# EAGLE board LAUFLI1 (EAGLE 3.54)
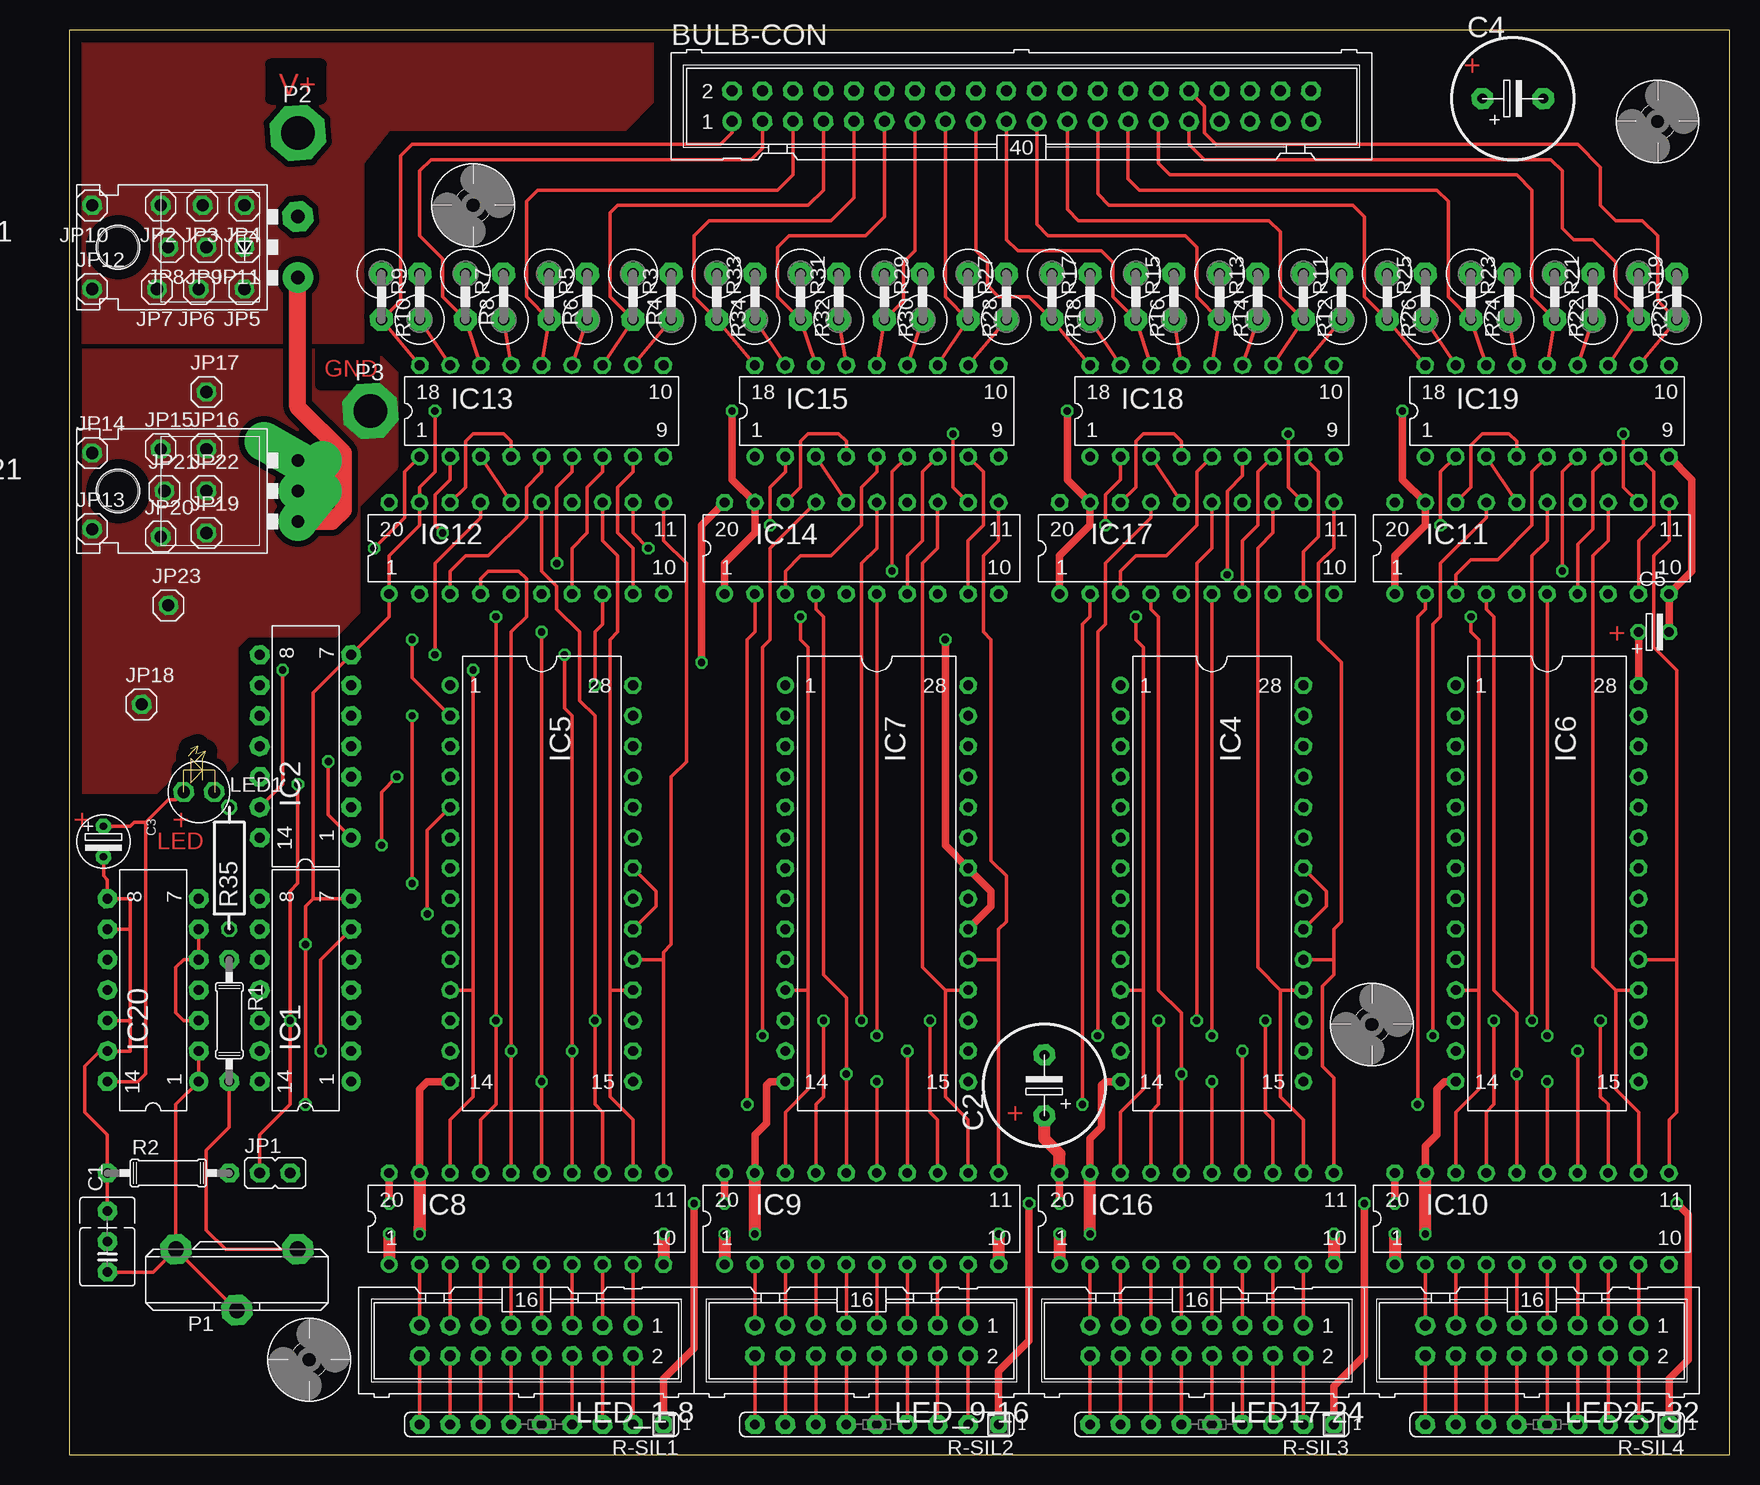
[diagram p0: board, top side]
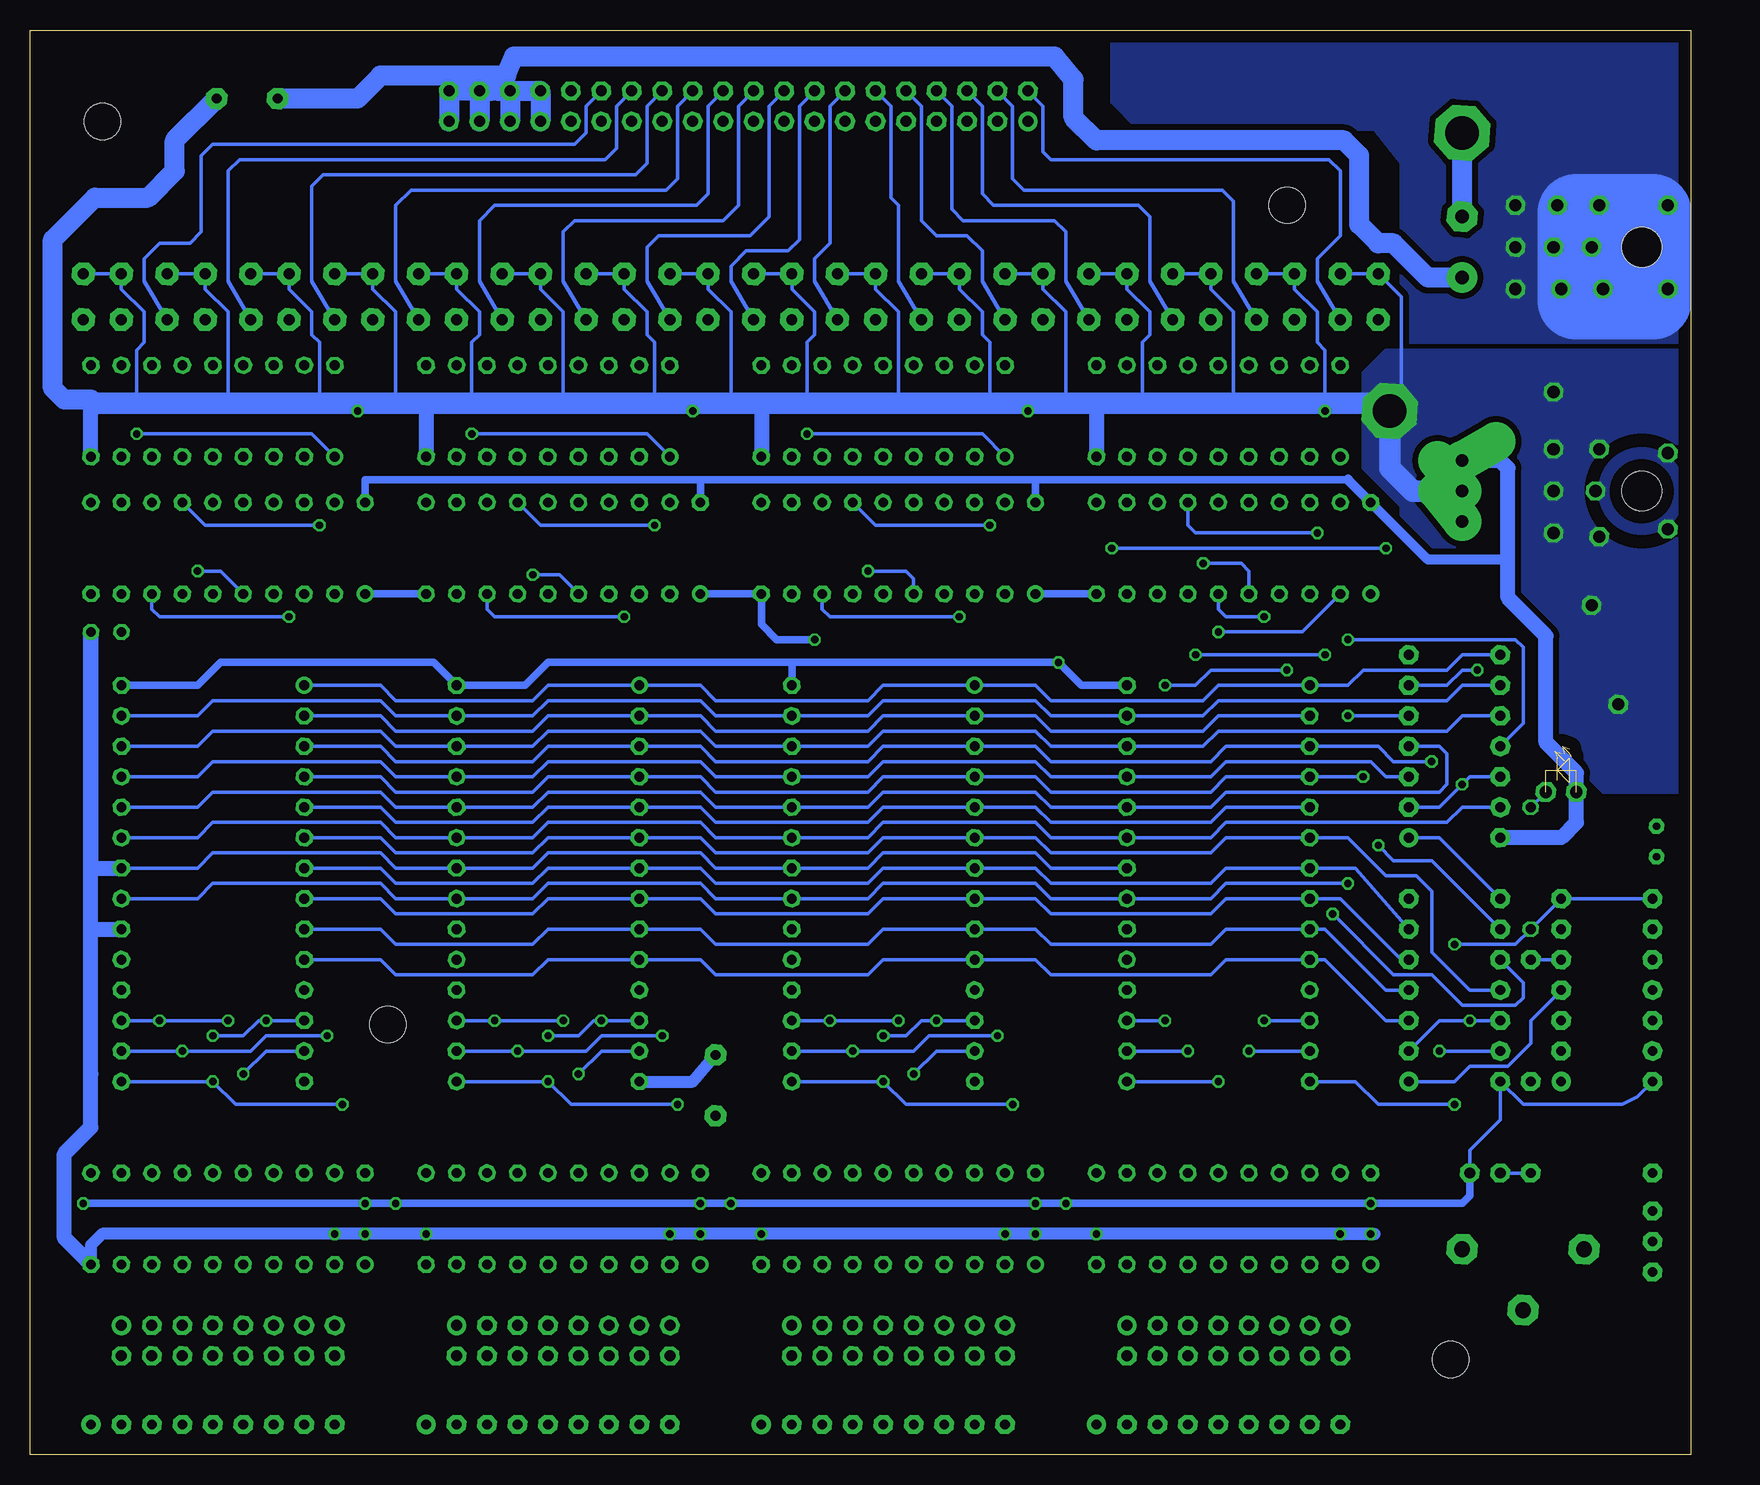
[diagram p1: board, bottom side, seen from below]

Size 138.43 x 118.75 mm. Coordinates in mm from the lower left corner, seen from the top.
Outline: 0,0 138.43,0 138.43,118.75 0,118.75 0,0
Copper layers used: Top, Bottom
tRestrict: area 16.8,113 to 21,115.9; area 21,89.2 to 25.4,92.1

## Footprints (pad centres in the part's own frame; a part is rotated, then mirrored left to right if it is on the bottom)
40 = drill 0.914 pad 1.6 round:  -24.13,-1.27 | drill 0.914 pad 1.6 octagon:  -24.13,1.27;  -21.59,-1.27;  -21.59,1.27;  -19.05,-1.27;  -19.05,1.27;  -16.51,-1.27;  -16.51,1.27;  -13.97,-1.27;  -13.97,1.27;  -11.43,-1.27;  -11.43,1.27;  -8.89,-1.27;  -8.89,1.27;  -6.35,-1.27;  -6.35,1.27;  -3.81,-1.27;  -3.81,1.27;  -1.27,-1.27;  -1.27,1.27;  1.27,-1.27;  1.27,1.27;  3.81,-1.27;  3.81,1.27;  6.35,-1.27;  6.35,1.27;  8.89,-1.27;  8.89,1.27;  11.43,1.27;  11.43,-1.27;  13.97,-1.27;  13.97,1.27;  16.51,1.27;  16.51,-1.27;  19.05,-1.27;  19.05,1.27;  21.59,1.27;  21.59,-1.27;  24.13,-1.27;  24.13,1.27
,5/5-5 = drill 0.813 pad 1.6 octagon:  -2.54,0;  2.54,0;  0,0
ELK5 = drill 0.813 pad 1.778 octagon:  -2.54,0;  2.54,0
ELK2,5 = drill 0.61 pad 1.27 octagon:  -1.27,0;  1.27,0
ELK2,5' = drill 0.813 pad 1.3 octagon:  0,0;  2.54,0
220ACK = drill 1.118 pad 2.54 round:  -2.54,-3.81 | drill 1.118 pad 2.54 octagon:  2.54,-3.81 | hole 3.302: 0,11.176
L14 = drill 0.813 pad 1.6 round:  -7.62,-3.81 | drill 0.813 pad 1.6 octagon:  -5.08,-3.81;  -2.54,-3.81;  0,-3.81;  2.54,-3.81;  5.08,-3.81;  7.62,-3.81;  7.62,3.81;  5.08,3.81;  2.54,3.81;  0,3.81;  -2.54,3.81;  -5.08,3.81;  -7.62,3.81
L28 = drill 0.813 pad 1.422 round:  -16.51,-7.62 | drill 0.813 pad 1.422 octagon:  -13.97,-7.62;  -11.43,-7.62;  -8.89,-7.62;  -6.35,-7.62;  -3.81,-7.62;  -1.27,-7.62;  1.27,-7.62;  3.81,-7.62;  6.35,-7.62;  8.89,-7.62;  11.43,-7.62;  13.97,-7.62;  16.51,-7.62;  16.51,7.62;  13.97,7.62;  11.43,7.62;  8.89,7.62;  6.35,7.62;  3.81,7.62;  1.27,7.62;  -1.27,7.62;  -3.81,7.62;  -6.35,7.62;  -8.89,7.62;  -11.43,7.62;  -13.97,7.62;  -16.51,7.62
L20 = drill 0.813 pad 1.397 round:  -11.43,-3.81 | drill 0.813 pad 1.397 octagon:  -8.89,-3.81;  -6.35,-3.81;  -3.81,-3.81;  -1.27,-3.81;  1.27,-3.81;  3.81,-3.81;  6.35,-3.81;  8.89,-3.81;  11.43,-3.81;  11.43,3.81;  8.89,3.81;  6.35,3.81;  3.81,3.81;  1.27,3.81;  -1.27,3.81;  -3.81,3.81;  -6.35,3.81;  -8.89,3.81;  -11.43,3.81
L18 = drill 0.813 pad 1.422 round:  -10.16,-3.81 | drill 0.813 pad 1.422 octagon:  -7.62,-3.81;  -5.08,-3.81;  -2.54,-3.81;  0,-3.81;  2.54,-3.81;  5.08,-3.81;  7.62,-3.81;  10.16,-3.81;  10.16,3.81;  7.62,3.81;  5.08,3.81;  2.54,3.81;  0,3.81;  -2.54,3.81;  -5.08,3.81;  -7.62,3.81;  -10.16,3.81
L14' = drill 0.813 pad 1.6 round:  -7.62,-3.81 | drill 0.813 pad 1.6 octagon:  -5.08,-3.81;  7.62,-3.81;  7.62,3.81;  -2.54,-3.81;  0,-3.81;  5.08,-3.81;  2.54,-3.81;  5.08,3.81;  2.54,3.81;  0,3.81;  -2.54,3.81;  -5.08,3.81;  -7.62,3.81
XXL = drill 1.016 pad 3.251 offset:  -2.54,-3.81;  0,-3.81;  2.54,-3.81 | hole 3.302: 0,11.176
1 = drill 0.914 pad 1.6 octagon:  0,-1.27;  0,1.27
01 = drill 1.016 pad 1.6 octagon:  0,0
D-5 = drill 1.016 pad 1.676 octagon:  0,0;  2.54,0
16 = drill 0.914 pad 1.6 round:  -8.89,-1.27 | drill 0.914 pad 1.6 octagon:  -8.89,1.27;  -6.35,-1.27;  -6.35,1.27;  -3.81,-1.27;  -3.81,1.27;  -1.27,-1.27;  -1.27,1.27;  1.27,-1.27;  1.27,1.27;  3.81,-1.27;  3.81,1.27;  6.35,-1.27;  6.35,1.27;  8.89,-1.27;  8.89,1.27
15 = drill 1.321 pad 2.54 octagon:  -5.08,-2.54;  5.08,-2.54;  0,2.54
N3_81 = drill 2.794 pad 4.572 octagon:  0,0
07/10 = drill 0.813 pad 1.6 octagon:  -5.08,0;  5.08,0
11V = drill 0.914 pad 1.905 octagon:  -2.54,0;  1.27,0
0 = drill 0.813 pad 1.3 octagon:  0,0;  10.16,0
L9 = drill 0.813 pad 1.6 round:  -10.16,0 | drill 0.813 pad 1.6 octagon:  -7.62,0;  -5.08,0;  -2.54,0;  0,0;  2.54,0;  5.08,0;  7.62,0;  10.16,0
3,0 = hole 3.023: 0,0

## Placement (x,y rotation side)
BULB-CON  [40]  79.38,112.39 0 top
C1  330nF  [,5/5-5]  3.17,17.78 90 top
C2  1000uF/6.3V  [ELK5]  81.28,30.8 90 top
C3  4u7 Tantal  [ELK2,5]  2.86,51.12 270 top
C4  470uF/16V  [ELK5]  120.33,113.03 0 top
C5  4u7  [ELK2,5']  130.81,68.58 0 top
D1  MBR760  [220ACK]  15.24,100.65 90 top
IC1  74393  [L14]  19.68,38.73 90 top
IC2  74393  [L14]  19.68,59.05 90 top
IC4  27512  [L28]  95.25,47.62 270 top
IC5  27512  [L28]  39.37,47.62 270 top
IC6  27512  [L28]  123.19,47.62 270 top
IC7  27512  [L28]  67.31,47.62 270 top
IC8  74245  [L20]  38.1,19.68 0 top
IC9  74245  [L20]  66.04,19.68 0 top
IC10  74245  [L20]  121.92,19.68 0 top
IC11  74240  [L20]  121.92,75.56 0 top
IC12  74240  [L20]  38.1,75.56 0 top
IC13  ULN2803A  [L18]  39.37,87 0 top
IC14  74240  [L20]  66.04,75.56 0 top
IC15  ULN2803A  [L18]  67.31,87 0 top
IC16  74245  [L20]  93.98,19.68 0 top
IC17  74240  [L20]  93.98,75.56 0 top
IC18  ULN2803A  [L18]  95.25,87 0 top
IC19  ULN2803A  [L18]  123.19,87 0 top
IC20  4093  [L14']  6.99,38.73 90 top
IC21  7805  [XXL]  15.24,80.33 90 top
JP1  RESET  [1]  17.14,23.5 270 top
JP2  PINHD-1X1  [01]  7.62,104.14 180 top
JP3  PINHD-1X1  [01]  11.11,104.14 180 top
JP4  PINHD-1X1  [01]  14.61,104.14 180 top
JP5  PINHD-1X1  [01]  14.61,97.16 180 top
JP6  PINHD-1X1  [01]  10.79,97.16 180 top
JP7  PINHD-1X1  [01]  7.3,97.16 180 top
JP8  PINHD-1X1  [01]  8.26,100.65 180 top
JP9  PINHD-1X1  [01]  11.43,100.65 180 top
JP10  PINHD-1X1  [01]  1.91,104.14 180 top
JP11  PINHD-1X1  [01]  14.61,100.65 180 top
JP12  PINHD-1X1  [01]  1.91,97.16 0 top
JP13  PINHD-1X1  [01]  1.91,77.15 0 top
JP14  PINHD-1X1  [01]  1.91,83.5 0 top
JP15  PINHD-1X1  [01]  7.62,83.82 0 top
JP16  PINHD-1X1  [01]  11.43,83.82 0 top
JP17  PINHD-1X1  [01]  11.43,88.58 0 top
JP18  PINHD-1X1  [01]  6.03,62.55 0 top
JP19  PINHD-1X1  [01]  11.43,76.83 0 top
JP20  PINHD-1X1  [01]  7.62,76.52 0 top
JP21  PINHD-1X1  [01]  7.94,80.33 0 top
JP22  PINHD-1X1  [01]  11.43,80.33 0 top
JP23  PINHD-1X1  [01]  8.26,70.8 0 top
LED1  Power  [D-5]  9.53,55.24 0 top
LED17-24  ML16  [16]  93.98,9.53 180 top
LED25-32  ML16  [16]  121.92,9.53 180 top
LED_1-8  ML16  [16]  38.1,9.53 180 top
LED_9-16  ML16  [16]  66.04,9.53 180 top
P1  500K  [15]  13.97,14.61 180 top
P2  [N3_81]  19.05,110.17 0 top
P3  [N3_81]  25.08,87 0 top
R1  1K8  [07/10]  13.34,36.2 270 top
R2  330R  [07/10]  8.26,23.5 0 top
R3  220 Ohm  [11V]  50.16,97.16 90 top
R4  220 Ohm  [11V]  46.99,95.89 270 top
R5  220 Ohm  [11V]  43.18,97.16 90 top
R6  220 Ohm  [11V]  40.01,95.89 270 top
R7  220 Ohm  [11V]  36.2,97.16 90 top
R8  220 Ohm  [11V]  33.02,95.89 270 top
R9  220 Ohm  [11V]  29.21,97.16 90 top
R10  220 Ohm  [11V]  26.04,95.89 270 top
R11  220 Ohm  [11V]  106.05,97.16 90 top
R12  220 Ohm  [11V]  102.87,95.89 270 top
R13  220 Ohm  [11V]  99.06,97.16 90 top
R14  220 Ohm  [11V]  95.89,95.89 270 top
R15  220 Ohm  [11V]  92.08,97.16 90 top
R16  220 Ohm  [11V]  88.9,95.89 270 top
R17  220 Ohm  [11V]  85.09,97.16 90 top
R18  220 Ohm  [11V]  81.92,95.89 270 top
R19  220 Ohm  [11V]  133.99,97.16 90 top
R20  220 Ohm  [11V]  130.81,95.89 270 top
R21  220 Ohm  [11V]  127,97.16 90 top
R22  220 Ohm  [11V]  123.83,95.89 270 top
R23  220 Ohm  [11V]  120.02,97.16 90 top
R24  220 Ohm  [11V]  116.84,95.89 270 top
R25  220 Ohm  [11V]  113.03,97.16 90 top
R26  220 Ohm  [11V]  109.86,95.89 270 top
R27  220 Ohm  [11V]  78.11,97.16 90 top
R28  220 Ohm  [11V]  74.93,95.89 270 top
R29  220 Ohm  [11V]  71.12,97.16 90 top
R30  220 Ohm  [11V]  67.94,95.89 270 top
R31  220 Ohm  [11V]  64.14,97.16 90 top
R32  220 Ohm  [11V]  60.96,95.89 270 top
R33  220 Ohm  [11V]  57.15,97.16 90 top
R34  220 Ohm  [11V]  53.98,95.89 270 top
R35  330  [0]  13.34,43.81 90 top
R-SIL1  8x220 Ohm  [L9]  39.37,2.54 180 top
R-SIL2  8x220 Ohm  [L9]  67.31,2.54 180 top
R-SIL3  8x220 Ohm  [L9]  95.25,2.54 180 top
R-SIL4  8x220 Ohm  [L9]  123.19,2.54 180 top
U$2  [3,0]  20,7.94 0 top
U$3  [3,0]  33.66,104.14 0 top
U$4  [3,0]  108.58,35.88 0 top
U$5  [3,0]  132.4,111.12 0 top

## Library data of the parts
BULB-CON LED17-24 LED25-32 LED_1-8 LED_9-16 = CON-ML
C1 = CAP
C2-C4 P2 P3 R35 = MATHIAS2
C5 LED1 = MATHIA2A
D1 = DIODE
IC1 IC2 IC8-IC12 IC14 IC16 IC17 = 74XX
IC4-IC7 = MEMORY
IC13 IC15 IC18 IC19 = ULN
IC20 = 40XX
IC21 = V-REG
JP1 = JUMPS
JP2-JP23 = PINHEAD
P1 = TRIMPOT
R1-R34 = R
R-SIL1-R-SIL4 = R-SIL
U$2-U$5 = HOLES

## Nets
+5V: C2. C3. C5. IC1. IC2. IC4. IC5. IC6. IC7. IC8. IC9. IC10. IC11. IC12. IC14. IC16. IC17. IC20. IC21. JP1. LED1. R-SIL1. R-SIL2. R-SIL3. R-SIL4.
A0: IC1. IC4. IC5. IC6. IC7.
A1: IC1. IC4. IC5. IC6. IC7.
A2: IC1. IC4. IC5. IC6. IC7.
A3: IC1. IC4. IC5. IC6. IC7.
A4: IC1. IC4. IC5. IC6. IC7.
A5: IC1. IC4. IC5. IC6. IC7.
A6: IC1. IC4. IC5. IC6. IC7.
A7: IC1. IC2. IC4. IC5. IC6. IC7.
A8: IC2. IC4. IC5. IC6. IC7.
A9: IC2. IC4. IC5. IC6. IC7.
A10: IC2. IC4. IC5. IC6. IC7.
A11: IC2. IC4. IC5. IC6. IC7.
A12: IC2. IC4. IC5. IC6. IC7.
A13: IC2. IC4. IC5. IC6. IC7.
A14: IC2. IC4. IC5. IC6. IC7.
A15: IC2. IC4. IC5. IC6. IC7.
BULB1: BULB-CON. IC13. R10.
BULB2: BULB-CON. IC13. R9.
BULB3: BULB-CON. IC13. R8.
BULB4: BULB-CON. IC13. R7.
BULB5: BULB-CON. IC13. R6.
BULB6: BULB-CON. IC13. R5.
BULB7: BULB-CON. IC13. R4.
BULB8: BULB-CON. IC13. R3.
BULB9: BULB-CON. IC15. R34.
BULB10: BULB-CON. IC15. R33.
BULB11: BULB-CON. IC15. R32.
BULB12: BULB-CON. IC15. R31.
BULB13: BULB-CON. IC15. R30.
BULB14: BULB-CON. IC15. R29.
BULB15: BULB-CON. IC15. R28.
BULB16: BULB-CON. IC15. R27.
BULB17: BULB-CON. IC18. R18.
BULB18: BULB-CON. IC18. R17.
BULB19: BULB-CON. IC18. R16.
BULB20: BULB-CON. IC18. R15.
BULB21: BULB-CON. IC18. R14.
BULB22: BULB-CON. IC18. R13.
BULB23: BULB-CON. IC18. R12.
BULB24: BULB-CON. IC18. R11.
BULB25: BULB-CON. IC19. R26.
BULB26: BULB-CON. IC19. R25.
BULB27: BULB-CON. IC19. R24.
BULB28: BULB-CON. IC19. R23.
BULB29: BULB-CON. IC19. R22.
BULB30: BULB-CON. IC19. R21.
BULB31: BULB-CON. IC19. R20.
BULB32: BULB-CON. IC19. R19.
CLOCK: IC1. IC20.
D1: IC5. IC8. IC12.
D2: IC5. IC8. IC12.
D3: IC5. IC8. IC12.
D4: IC5. IC8. IC12.
D5: IC5. IC8. IC12.
D6: IC5. IC8. IC12.
D7: IC5. IC8. IC12.
D8: IC5. IC8. IC12.
D9: IC7. IC9. IC14.
D10: IC7. IC9. IC14.
D11: IC7. IC9. IC14.
D12: IC7. IC9. IC14.
D13: IC7. IC9. IC14.
D14: IC7. IC9. IC14.
D15: IC7. IC9. IC14.
D16: IC7. IC9. IC14.
D17: IC4. IC16. IC17.
D18: IC4. IC16. IC17.
D19: IC4. IC16. IC17.
D20: IC4. IC16. IC17.
D21: IC4. IC16. IC17.
D22: IC4. IC16. IC17.
D23: IC4. IC16. IC17.
D24: IC4. IC16. IC17.
D25: IC6. IC10. IC11.
D26: IC6. IC10. IC11.
D27: IC6. IC10. IC11.
D28: IC6. IC10. IC11.
D29: IC6. IC10. IC11.
D30: IC6. IC10. IC11.
D31: IC6. IC10. IC11.
D32: IC6. IC10. IC11.
GND: C1. C2. C3. C4. C5. IC1. IC2. IC4. IC5. IC6. IC7. IC8. IC9. IC10. IC11. IC12. IC13. IC14. IC15. IC16. IC17. IC18. IC19. IC20. IC21. JP13. JP14. JP15. JP16. JP17. JP18. JP19. JP20. JP21. JP22. JP23. P3. R2. R3. R4. R5. R6. R7. R8. R9. R10. R11. R12. R13. R14. R15. R16. R17. R18. R19. R20. R21. R22. R23. R24. R25. R26. R27. R28. R29. R30. R31. R32. R33. R34. R35.
N$1: IC20. R1.
N$2: P1. R1.
N$3: IC1. IC2. JP1. R2.
N$4: IC9. LED_9-16.
N$5: IC9. LED_9-16.
N$6: C1. IC20. P1.
N$7: IC9. LED_9-16.
N$8: IC9. LED_9-16.
N$9: IC9. LED_9-16.
N$10: IC9. LED_9-16.
N$11: IC9. LED_9-16.
N$12: IC9. LED_9-16.
N$13: IC8. LED_1-8.
N$14: IC8. LED_1-8.
N$15: IC8. LED_1-8.
N$16: IC8. LED_1-8.
N$17: IC8. LED_1-8.
N$18: IC8. LED_1-8.
N$19: IC8. LED_1-8.
N$20: IC8. LED_1-8.
N$21: LED_1-8. R-SIL1.
N$22: LED_1-8. R-SIL1.
N$23: LED_1-8. R-SIL1.
N$24: LED_1-8. R-SIL1.
N$25: LED_1-8. R-SIL1.
N$26: LED_1-8. R-SIL1.
N$27: LED_1-8. R-SIL1.
N$28: LED_1-8. R-SIL1.
N$29: LED_9-16. R-SIL2.
N$30: LED_9-16. R-SIL2.
N$31: LED_9-16. R-SIL2.
N$32: LED_9-16. R-SIL2.
N$33: LED_9-16. R-SIL2.
N$34: LED_9-16. R-SIL2.
N$35: LED_9-16. R-SIL2.
N$36: LED_9-16. R-SIL2.
N$37: IC14. IC15.
N$38: IC14. IC15.
N$39: IC14. IC15.
N$40: IC14. IC15.
N$41: IC14. IC15.
N$42: IC14. IC15.
N$43: IC14. IC15.
N$44: IC14. IC15.
N$45: IC16. LED17-24.
N$46: IC16. LED17-24.
N$47: IC16. LED17-24.
N$48: IC16. LED17-24.
N$49: IC16. LED17-24.
N$50: IC16. LED17-24.
N$51: IC16. LED17-24.
N$52: IC16. LED17-24.
N$53: IC10. LED25-32.
N$54: IC10. LED25-32.
N$55: IC10. LED25-32.
N$56: IC10. LED25-32.
N$57: IC10. LED25-32.
N$58: IC10. LED25-32.
N$59: IC10. LED25-32.
N$60: IC10. LED25-32.
N$61: LED25-32. R-SIL4.
N$62: LED25-32. R-SIL4.
N$63: LED25-32. R-SIL4.
N$64: LED25-32. R-SIL4.
N$65: LED25-32. R-SIL4.
N$66: LED25-32. R-SIL4.
N$67: LED25-32. R-SIL4.
N$68: LED25-32. R-SIL4.
N$69: IC11. IC19.
N$70: IC11. IC19.
N$71: IC11. IC19.
N$72: IC11. IC19.
N$73: IC11. IC19.
N$74: IC11. IC19.
N$75: IC11. IC19.
N$76: IC11. IC19.
N$77: LED1. R35.
N$78: D1. P2.
N$101: IC12. IC13.
N$102: IC12. IC13.
N$103: IC12. IC13.
N$104: IC12. IC13.
N$105: IC12. IC13.
N$106: IC12. IC13.
N$107: IC12. IC13.
N$108: IC12. IC13.
N$109: LED17-24. R-SIL3.
N$110: LED17-24. R-SIL3.
N$111: LED17-24. R-SIL3.
N$112: LED17-24. R-SIL3.
N$113: LED17-24. R-SIL3.
N$114: LED17-24. R-SIL3.
N$115: LED17-24. R-SIL3.
N$116: LED17-24. R-SIL3.
N$117: IC17. IC18.
N$118: IC17. IC18.
N$119: IC17. IC18.
N$120: IC17. IC18.
N$121: IC17. IC18.
N$122: IC17. IC18.
N$123: IC17. IC18.
N$124: IC17. IC18.
P1: JP2. JP3. JP4. JP5. JP6. JP7. JP8. JP9. JP10. JP11. JP12.
V_IN: BULB-CON. C4. D1. IC21.

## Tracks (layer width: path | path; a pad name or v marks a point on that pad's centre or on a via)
+5V  (via drill 0.61 pad 1.02)
  Top 0.305: IC20. 5.71,31.11 6.35,31.75 6.35,52.7 | 6.35,52.7 8.26,54.61 8.89,54.61 9.53,55.24 | 6.35,52.7 5.4,52.7 5.08,52.39 2.86,52.39
  Top 0.61: IC14. 52.7,77.47 v52.7,66.04 | 49.53,2.54 49.53,6.35 52.07,8.89 v52.07,20.95 | v54.61,20.95 IC9. | v54.61,20.95 IC9. | v82.55,20.95 IC16. | v82.55,20.95 IC16. | v80.01,20.95 80.01,9.53 77.47,6.99 77.47,2.54 | v82.55,20.95 IC16. | 105.41,2.54 105.41,5.71 107.95,8.26 v107.95,20.95 | v133.99,20.95 134.94,20 134.94,7.94 133.35,6.35 133.35,2.54 | v54.61,20.95 IC9. | IC6. 130.81,68.58 | v110.49,20.95 IC10. v110.49,20.95 | v26.67,20.95 IC8. v26.67,20.95
  Top 1.016: 81.28,28.26 81.28,26.35 82.55,25.08 IC16.
  Bottom 0.305: 9.53,55.24 9.53,52.7 | IC20. 4.45,29.84 5.71,29.21 13.97,29.21 IC1. 15.88,27.94 18.41,25.4 JP1.
  Bottom 0.61: IC5. 50.8,64.14 v52.7,66.04 74.93,66.04 | IC12. 28.57,81.28 54.61,81.28 | 54.61,81.28 IC14. | 54.61,81.28 82.55,81.28 | 82.55,81.28 IC17. | 82.55,81.28 110.49,81.28 IC11. | IC6. 124.46,64.14 122.56,66.04 104.78,66.04 IC4. 97.16,64.14 95.25,66.04 74.93,66.04 | 74.93,66.04 IC7. | v54.61,20.95 v52.07,20.95 | v54.61,20.95 v80.01,20.95 v82.55,20.95 v107.95,20.95 | v107.95,20.95 v110.49,20.95 | v107.95,20.95 v133.99,20.95 | v54.61,20.95 v26.67,20.95 19.05,20.95 18.41,21.59 JP1.
  Bottom 0.813: 28.57,81.28 21.91,74.61 15.24,74.61 15.24,71.44
  Bottom 1.27: IC2. 10.79,51.44 9.53,52.7 9.53,56.83 12.06,59.37 12.06,68.26 15.24,71.44 15.24,82.23 15.88,82.87 IC21.
A0
  Bottom 0.305: 115.57,41.27 109.22,41.27 107.95,40.01 96.52,40.01 95.25,41.27 87.63,41.27 82.55,41.27 81.28,40.01 68.58,40.01 67.31,41.27 59.69,41.27 54.61,41.27 53.34,40.01 40.01,40.01 38.73,41.27 31.75,41.27 30.48,41.27 25.4,36.2 23.5,36.2
A1
  Bottom 0.305: 115.57,43.81 109.22,43.81 107.95,42.55 96.52,42.55 95.25,43.81 87.63,43.81 82.55,43.81 81.28,42.55 68.58,42.55 67.31,43.81 59.69,43.81 54.61,43.81 53.34,42.55 40.01,42.55 38.73,43.81 31.75,43.81 30.48,43.81 25.4,38.73 23.5,38.73
A2
  Bottom 0.305: 115.57,46.35 109.22,46.35 107.95,45.09 96.52,45.09 95.25,46.35 87.63,46.35 82.55,46.35 81.28,45.09 68.58,45.09 67.31,46.35 59.69,46.35 54.61,46.35 53.34,45.09 40.01,45.09 38.73,46.35 31.75,46.35 29.21,46.35 24.13,41.27 23.5,41.27
A3  (via drill 0.61 pad 1.02)
  Top 0.305: 23.5,43.81 20.95,41.27 v20.95,33.66
  Bottom 0.305: 115.57,48.9 109.22,48.9 107.95,47.62 96.52,47.62 95.25,48.9 87.63,48.9 82.55,48.9 81.28,47.62 68.58,47.62 67.31,48.9 59.69,48.9 54.61,48.9 53.34,47.62 40.01,47.62 38.73,48.9 31.75,48.9 27.94,48.9 23.5,43.81 | 15.88,33.66 v20.95,33.66
A4
  Bottom 0.305: 115.57,51.44 109.22,51.44 107.95,50.16 96.52,50.16 95.25,51.44 87.63,51.44 82.55,51.44 81.28,50.16 68.58,50.16 67.31,51.44 59.69,51.44 54.61,51.44 53.34,50.16 40.01,50.16 38.73,51.44 31.75,51.44 28.57,51.44 25.4,48.26 22.86,48.26 21.59,46.99 21.59,41.91 18.41,38.73 15.88,38.73
A5  (via drill 0.61 pad 1.02)
  Top 0.305: 31.75,53.98 29.84,52.07 v29.84,45.09
  Bottom 0.305: 115.57,53.98 109.22,53.98 107.95,52.7 96.52,52.7 95.25,53.98 87.63,53.98 82.55,53.98 81.28,52.7 68.58,52.7 67.31,53.98 59.69,53.98 54.61,53.98 53.34,52.7 40.01,52.7 38.73,53.98 31.75,53.98 | v29.84,45.09 24.77,40.01 21.59,40.01 19.05,37.47 14.61,37.47 13.97,38.1 13.97,39.37 15.88,41.27
A6  (via drill 0.61 pad 1.02)
  Top 0.305: v26.04,50.8 26.04,55.24 v27.3,56.52
  Bottom 0.305: 115.57,56.52 109.22,56.52 107.95,55.24 96.52,55.24 95.25,56.52 87.63,56.52 82.55,56.52 81.28,55.24 68.58,55.24 67.31,56.52 59.69,56.52 54.61,56.52 53.34,55.24 40.01,55.24 38.73,56.52 31.75,56.52 v27.3,56.52 | 15.88,43.81 21.59,49.53 24.77,49.53 v26.04,50.8
A7  (via drill 0.61 pad 1.02)
  Top 0.305: v21.59,57.78 21.59,53.34 23.5,51.44
  Bottom 0.305: 115.57,59.05 109.22,59.05 107.95,57.78 96.52,57.78 95.25,59.05 87.63,59.05 82.55,59.05 81.28,57.78 68.58,57.78 67.31,59.05 59.69,59.05 54.61,59.05 53.34,57.78 40.01,57.78 38.73,59.05 31.75,59.05 26.04,59.05 24.77,57.78 v21.59,57.78 | 23.5,51.44 20.95,51.44 15.88,46.35
A8
  Bottom 0.305: 130.81,56.52 124.46,56.52 123.19,57.78 109.22,57.78 107.95,56.52 102.87,56.52 96.52,56.52 95.25,57.78 82.55,57.78 81.28,56.52 74.93,56.52 68.58,56.52 67.31,57.78 54.61,57.78 53.34,56.52 46.99,56.52 40.01,56.52 38.73,57.78 26.67,57.78 25.4,56.52 23.5,56.52
A9
  Bottom 0.305: 130.81,53.98 124.46,53.98 123.19,55.24 109.22,55.24 107.95,53.98 102.87,53.98 96.52,53.98 95.25,55.24 82.55,55.24 81.28,53.98 74.93,53.98 68.58,53.98 67.31,55.24 54.61,55.24 53.34,53.98 46.99,53.98 40.01,53.98 38.73,55.24 20.95,55.24 20.32,55.88 20.32,58.42 20.95,59.05 23.5,59.05
A10  (via drill 0.61 pad 1.02)
  Top 0.305: v28.57,47.62 v28.57,61.59
  Bottom 0.305: 130.81,46.35 124.46,46.35 123.19,47.62 109.22,47.62 107.95,46.35 102.87,46.35 96.52,46.35 95.25,47.62 82.55,47.62 81.28,46.35 74.93,46.35 68.58,46.35 67.31,47.62 54.61,47.62 53.34,46.35 46.99,46.35 40.01,46.35 38.73,47.62 v28.57,47.62 | v28.57,61.59 23.5,61.59
A11  (via drill 0.61 pad 1.02)
  Top 0.305: 15.88,53.98 17.78,55.88 v17.78,65.41
  Bottom 0.305: 130.81,51.44 124.46,51.44 123.19,52.7 109.22,52.7 107.95,51.44 102.87,51.44 96.52,51.44 95.25,52.7 82.55,52.7 81.28,51.44 74.93,51.44 68.58,51.44 67.31,52.7 54.61,52.7 53.34,51.44 46.99,51.44 40.01,51.44 38.73,52.7 20.32,52.7 19.05,53.98 15.88,53.98 | v17.78,65.41 19.05,65.41 20.32,64.14 23.5,64.14
A12  (via drill 0.61 pad 1.02)
  Top 0.305: v28.57,67.94 28.57,64.77 31.75,61.59
  Bottom 0.305: 115.57,61.59 109.22,61.59 107.95,60.33 96.52,60.33 95.25,61.59 87.63,61.59 82.55,61.59 81.28,60.33 68.58,60.33 67.31,61.59 59.69,61.59 54.61,61.59 53.34,60.33 40.64,60.33 39.37,61.59 31.75,61.59 | 15.88,59.05 13.97,60.96 13.97,67.31 14.61,67.94 v28.57,67.94
A13
  Bottom 0.305: 130.81,59.05 124.46,59.05 123.19,60.33 109.22,60.33 107.95,59.05 102.87,59.05 96.52,59.05 95.25,60.33 82.55,60.33 81.28,59.05 74.93,59.05 68.58,59.05 67.31,60.33 54.61,60.33 53.34,59.05 46.99,59.05 40.64,59.05 39.37,60.33 20.32,60.33 19.05,61.59 15.88,61.59
A14
  Bottom 0.305: 130.81,61.59 124.46,61.59 123.19,62.87 109.22,62.87 107.95,61.59 102.87,61.59 96.52,61.59 95.25,62.87 82.55,62.87 81.28,61.59 74.93,61.59 68.58,61.59 67.31,62.87 54.61,62.87 53.34,61.59 46.99,61.59 40.64,61.59 39.37,62.87 20.32,62.87 19.05,64.14 15.88,64.14
A15
  Bottom 0.305: 15.88,66.67 19.05,66.67 20.32,65.41 27.3,65.41 28.57,64.14 31.75,64.14 39.37,64.14 40.64,62.87 53.34,62.87 54.61,64.14 59.69,64.14 67.31,64.14 68.58,62.87 81.28,62.87 82.55,64.14 87.63,64.14 95.25,64.14 96.52,62.87 107.95,62.87 109.22,64.14 115.57,64.14
BULB1
  Top 0.305: IC13. R10. 27.62,96.2 27.62,108.27 28.57,109.22 54.29,109.22 55.24,110.17 55.24,111.12
BULB2
  Top 0.305: 31.75,90.81 29.21,94.61
  Bottom 0.305: 29.21,94.61 31.11,97.79 31.11,99.69 29.21,101.6 29.21,107 30.16,107.95 53.34,107.95 53.98,108.58 53.98,112.39 55.24,113.67
BULB3
  Top 0.305: 34.29,90.81 R8. 31.11,96.52 31.11,99.69 29.21,101.6 29.21,107 30.16,107.95 56.83,107.95 57.78,108.9 57.78,111.12
BULB4
  Top 0.305: 36.83,90.81 36.2,94.61
  Bottom 0.305: 36.2,94.61 38.1,97.79 38.1,104.46 39.05,105.41 55.56,105.41 56.52,106.36 56.52,112.39 57.78,113.67
BULB5
  Top 0.305: 39.37,90.81 R6. 38.1,96.52 38.1,104.46 39.05,105.41 59.05,105.41 60.33,106.68 60.33,111.12
BULB6
  Top 0.305: 41.91,90.81 43.18,94.61
  Bottom 0.305: 43.18,94.61 45.09,97.79 45.09,103.19 46.04,104.14 58.1,104.14 59.05,105.09 59.05,112.39 60.33,113.67
BULB7
  Top 0.305: 44.45,90.81 R4. 45.09,96.52 45.09,103.5 45.72,104.14 61.59,104.14 62.87,105.41 62.87,111.12
BULB8
  Top 0.305: 46.99,90.81 50.16,94.61
  Bottom 0.305: 50.16,94.61 52.07,97.79 52.07,101.92 53.02,102.87 60.64,102.87 61.59,103.82 61.59,112.39 62.87,113.67
BULB9
  Top 0.305: IC15. R34. 52.07,96.52 52.07,101.6 53.34,102.87 63.5,102.87 65.41,104.78 65.41,111.12
BULB10
  Top 0.305: 59.69,90.81 57.15,94.61
  Bottom 0.305: 57.15,94.61 59.05,97.79 59.05,100.33 60.33,101.6 62.87,101.6 64.14,102.87 64.14,112.39 65.41,113.67
BULB11
  Top 0.305: 62.23,90.81 R32. 59.05,96.52 59.05,100.65 60.01,101.6 66.36,101.6 67.94,103.19 67.94,111.12
BULB12
  Top 0.305: 64.77,90.81 64.14,94.61
  Bottom 0.305: 64.14,94.61 66.04,97.79 66.04,104.14 66.67,104.78 66.67,112.39 67.94,113.67
BULB13
  Top 0.305: 67.31,90.81 R30. 69.53,96.2 69.53,99.38 70.48,100.33 70.48,111.12
BULB14
  Top 0.305: 69.85,90.81 71.12,94.61
  Bottom 0.305: 71.12,94.61 73.03,97.79 73.03,99.69 71.75,100.97 71.75,112.39 70.48,113.67
BULB15
  Top 0.305: 72.39,90.81 R28. 73.03,96.52 73.03,111.12
BULB16
  Top 0.305: 74.93,90.81 78.11,94.61
  Bottom 0.305: 78.11,94.61 80.01,97.79 80.01,99.06 78.74,100.33 75.25,100.33 74.3,101.28 74.3,112.39 73.03,113.67
BULB17
  Top 0.305: IC18. R18. 80.01,96.52 77.47,96.52 76.52,97.47 76.52,99.38 75.56,100.33 75.56,111.12
BULB18
  Top 0.305: 87.63,90.81 85.09,94.61
  Bottom 0.305: 85.09,94.61 87,97.79 87,100.65 86.04,101.6 78.42,101.6 76.83,103.19 76.83,112.39 75.56,113.67
BULB19
  Top 0.305: 90.17,90.81 R16. 87,96.52 87,99.38 86.04,100.33 79.06,100.33 78.11,101.28 78.11,111.12
BULB20
  Top 0.305: 92.71,90.81 92.08,94.61
  Bottom 0.305: 92.08,94.61 93.98,97.79 93.98,101.92 93.03,102.87 80.64,102.87 79.38,104.14 79.38,112.39 78.11,113.67
BULB21
  Top 0.305: 95.25,90.81 R14. 93.98,96.52 93.98,100.65 93.03,101.6 81.6,101.6 80.64,102.55 80.64,111.12
BULB22
  Top 0.305: 97.79,90.81 99.06,94.61
  Bottom 0.305: 99.06,94.61 100.97,97.79 100.97,102.87 99.69,104.14 82.87,104.14 81.92,105.09 81.92,112.39 80.64,113.67
BULB23
  Top 0.305: 100.33,90.81 R12. 100.97,96.52 100.97,101.92 100.01,102.87 84.14,102.87 83.19,103.82 83.19,111.12
BULB24
  Top 0.305: 106.05,94.61 102.87,90.81
  Bottom 0.305: 106.05,94.61 107.95,97.79 107.95,104.14 106.68,105.41 85.41,105.41 84.45,106.36 84.45,112.39 83.19,113.67
BULB25
  Top 0.305: IC19. R26. 107.95,96.52 107.95,103.19 107,104.14 86.68,104.14 85.72,105.09 85.72,111.12
BULB26
  Top 0.305: 113.03,94.61 115.57,90.81
  Bottom 0.305: 113.03,94.61 114.94,97.79 114.94,105.73 113.98,106.68 87.95,106.68 87,107.63 87,112.39 85.72,113.67
BULB27
  Top 0.305: 118.11,90.81 R24. 114.94,96.52 114.94,104.46 113.98,105.41 89.22,105.41 88.27,106.36 88.27,111.12
BULB28
  Top 0.305: 120.02,94.61 120.65,90.81
  Bottom 0.305: 120.02,94.61 121.92,97.79 121.92,107 120.97,107.95 90.49,107.95 89.53,108.9 89.53,112.39 88.27,113.67
BULB29
  Top 0.305: 123.19,90.81 R22. 121.92,96.52 121.92,105.41 120.65,106.68 91.76,106.68 90.81,107.63 90.81,111.12
BULB30
  Top 0.305: 127,94.61 125.73,90.81
  Bottom 0.305: 127,94.61 128.91,97.79 128.91,99.69 127.64,100.97 125.09,100.97 124.14,101.92 124.14,108.27 123.19,109.22 93.03,109.22 92.08,110.17 92.08,112.39 90.81,113.67
BULB31
  Top 0.305: 128.27,90.81 R20. 128.91,96.52 128.91,99.38 127,101.28 125.41,101.28 124.46,102.23 124.46,107 123.51,107.95 94.61,107.95 93.34,109.22 93.34,111.12
BULB32
  Top 0.305: 130.81,90.81 133.99,94.61 132.4,96.2 132.4,101.6 131.13,102.87 128.91,102.87 127.64,104.14 127.64,107.31 125.73,109.22 95.57,109.22 94.61,110.17 94.61,112.39 93.34,113.67
CLOCK
  Bottom 0.305: 10.79,38.73 13.34,36.2 13.34,34.29 15.24,32.38 18.41,32.38 19.68,31.11 23.5,31.11
D1  (via drill 0.61 pad 1.02)
  Top 0.305: 31.75,23.5 31.75,27.94 33.66,29.84 33.66,38.73 | 33.66,38.73 31.75,38.73 | 33.66,38.73 v33.66,65.41 | 44.45,71.75 44.45,69.22 43.81,68.58 v43.81,64.14
  Bottom 0.305: v43.81,64.14 41.27,64.14 40.01,65.41 v33.66,65.41
D2  (via drill 0.61 pad 1.02)
  Top 0.305: 34.29,23.5 34.29,27.94 35.56,29.21 v35.56,36.2 v35.56,69.85
  Bottom 0.305: v35.56,36.2 31.75,36.2 | v35.56,69.85 38.73,69.85 39.37,70.48 39.37,71.75
D3  (via drill 0.61 pad 1.02)
  Top 0.305: 36.83,23.5 v36.83,33.66 36.83,68.58 38.1,69.85 38.1,73.03 37.47,73.66 34.92,73.66 34.29,73.03 34.29,71.75
  Bottom 0.305: v36.83,33.66 31.75,33.66 v36.83,33.66
D4  (via drill 0.61 pad 1.02)
  Top 0.305: 39.37,23.5 v39.37,31.11 v39.37,68.58
  Bottom 0.305: 29.21,71.75 32.38,68.58 v39.37,68.58 | v39.37,31.11 46.99,31.11 v39.37,31.11
D5  (via drill 0.61 pad 1.02)
  Top 0.305: 41.91,23.5 v41.91,33.66 41.91,61.59 41.27,62.23 v41.27,66.67 | v30.48,66.67 30.48,74.3 34.29,78.11 34.29,79.38
  Bottom 0.305: v41.27,66.67 v30.48,66.67 | v41.91,33.66 46.99,33.66 v41.91,33.66
D6  (via drill 0.61 pad 1.02)
  Top 0.305: 44.45,23.5 44.45,28.57 43.81,29.21 v43.81,36.2 43.81,61.59 42.55,62.87 42.55,68.58 40.64,70.48 40.64,72.39 39.37,73.66 39.37,79.38
  Bottom 0.305: v43.81,36.2 46.99,36.2 v43.81,36.2
D7
  Top 0.305: 46.99,23.5 46.99,27.94 45.09,29.84 45.09,38.73 | 45.09,38.73 46.99,38.73 | 44.45,79.38 44.45,76.2 45.72,74.93 45.72,68.58 45.09,67.94 45.09,38.73
D8
  Top 0.305: 49.53,23.5 49.53,41.27 | 49.53,41.27 46.99,41.27 | 49.53,41.27 49.53,41.91 50.16,42.55 50.16,56.52 51.44,57.78 51.44,74.3 49.53,76.2 49.53,79.38
D9  (via drill 0.61 pad 1.02)
  Top 0.305: v60.96,69.85 60.96,67.94 61.59,67.31 61.59,38.73 | 61.59,38.73 59.69,38.73 | 61.59,38.73 61.59,30.48 59.69,28.57 59.69,23.5
  Bottom 0.305: 72.39,71.75 72.39,70.48 71.75,69.85 v60.96,69.85
D10  (via drill 0.61 pad 1.02)
  Top 0.305: v67.31,34.92 67.31,71.75 | 62.23,23.5 62.23,29.21 62.87,29.84 v62.87,36.2
  Bottom 0.305: v67.31,34.92 65.41,34.92 64.14,36.2 v62.87,36.2 59.69,36.2
D11  (via drill 0.61 pad 1.02)
  Top 0.305: 62.23,71.75 62.23,70.48 62.87,69.85 62.87,40.01 64.77,38.1 v64.77,31.75 64.77,23.5
  Bottom 0.305: v64.77,31.75 62.87,33.66 59.69,33.66
D12  (via drill 0.61 pad 1.02)
  Top 0.305: 57.15,71.75 57.15,68.58 56.52,67.94 v56.52,29.21 | v67.31,31.11 67.31,23.5
  Bottom 0.305: v67.31,31.11 74.93,31.11 v67.31,31.11 | v67.31,31.11 65.41,29.21 v56.52,29.21
D13  (via drill 0.61 pad 1.02)
  Top 0.305: 62.23,79.38 58.42,75.56 58.42,67.94 57.78,67.31 v57.78,34.92 | v69.85,33.66 69.85,23.5
  Bottom 0.305: v69.85,33.66 74.93,33.66 v69.85,33.66 | v69.85,33.66 64.77,33.66 63.5,34.92 v57.78,34.92
D14  (via drill 0.61 pad 1.02)
  Top 0.305: 67.31,79.38 67.31,75.56 66.04,74.3 v66.04,36.2 | 72.39,23.5 72.39,27.94 71.75,28.57 v71.75,36.2
  Bottom 0.305: v66.04,36.2 v71.75,36.2 74.93,36.2
D15
  Top 0.305: 72.39,79.38 72.39,75.56 71.12,74.3 71.12,40.64 73.03,38.73 | 74.93,23.5 74.93,27.94 73.03,29.84 73.03,38.73 | 73.03,38.73 74.93,38.73
D16
  Top 0.305: 77.47,79.38 77.47,76.2 76.2,74.93 76.2,68.58 76.83,67.94 76.83,49.53 78.11,48.26 78.11,44.45 77.47,43.81 77.47,41.27 | 77.47,23.5 77.47,41.27 | 77.47,41.27 74.93,41.27
D17  (via drill 0.61 pad 1.02)
  Top 0.305: v88.9,69.85 88.9,67.94 89.53,67.31 89.53,38.73 | 89.53,38.73 87.63,38.73 | 89.53,38.73 89.53,30.48 87.63,28.57 87.63,23.5
  Bottom 0.305: 100.33,71.75 100.33,70.48 99.69,69.85 v88.9,69.85
D18  (via drill 0.61 pad 1.02)
  Top 0.305: v95.25,34.92 95.25,71.75 | 90.17,23.5 90.17,28.57 90.81,29.21 v90.81,36.2
  Bottom 0.305: v95.25,34.92 92.71,34.92 91.44,36.2 v90.81,36.2 87.63,36.2
D19  (via drill 0.61 pad 1.02)
  Top 0.305: 90.17,71.75 90.17,70.48 90.81,69.85 90.81,38.73 92.71,36.83 v92.71,31.75 92.71,23.5
  Bottom 0.305: 87.63,33.66 90.81,33.66 v92.71,31.75
D20  (via drill 0.61 pad 1.02)
  Top 0.305: 85.09,71.75 85.09,69.85 84.45,69.22 v84.45,29.21 | v95.25,31.11 95.25,23.5
  Bottom 0.305: v84.45,29.21 93.34,29.21 v95.25,31.11 102.87,31.11
D21  (via drill 0.61 pad 1.02)
  Top 0.305: 90.17,79.38 90.17,78.11 86.36,74.3 86.36,69.22 85.72,68.58 v85.72,34.92 | v97.79,33.66 97.79,23.5
  Bottom 0.305: v97.79,33.66 102.87,33.66 92.08,33.66 90.81,34.92 v85.72,34.92
D22  (via drill 0.61 pad 1.02)
  Top 0.305: 95.25,79.38 95.25,75.56 93.98,74.3 v93.98,36.2 | 100.33,23.5 100.33,27.94 99.69,28.57 v99.69,36.2
  Bottom 0.305: v99.69,36.2 102.87,36.2 v99.69,36.2 | v99.69,36.2 v93.98,36.2
D23
  Top 0.305: 100.33,79.38 100.33,76.83 99.06,75.56 99.06,40.64 100.97,38.73 | 102.87,23.5 102.87,27.94 100.97,29.84 100.97,38.73 | 100.97,38.73 102.87,38.73
D24
  Top 0.305: 105.41,23.5 105.41,31.43 104.46,32.38 104.46,39.05 105.41,40.01 105.41,41.27 | 105.41,41.27 102.87,41.27 | 105.41,41.27 105.41,43.81 106.05,44.45 106.05,66.04 104.14,67.94 104.14,74.3 105.41,75.56 105.41,79.38
D25  (via drill 0.61 pad 1.02)
  Top 0.305: v116.84,69.85 116.84,68.58 117.47,67.94 117.47,38.73 | 115.57,23.5 115.57,28.57 117.47,30.48 117.47,38.73 | 117.47,38.73 115.57,38.73
  Bottom 0.305: 128.27,71.75 128.27,70.48 127.64,69.85 v116.84,69.85
D26  (via drill 0.61 pad 1.02)
  Top 0.305: 118.11,23.5 118.11,28.57 118.75,29.21 v118.75,36.2 | v123.19,34.92 123.19,71.75
  Bottom 0.305: v118.75,36.2 115.57,36.2 119.38,36.2 120.65,34.92 v123.19,34.92
D27  (via drill 0.61 pad 1.02)
  Top 0.305: 118.11,71.75 118.11,70.48 118.75,69.85 118.75,38.73 120.65,36.83 v120.65,31.75 120.65,23.5
  Bottom 0.305: 115.57,33.66 118.75,33.66 v120.65,31.75
D28  (via drill 0.61 pad 1.02)
  Top 0.305: 113.03,71.75 113.03,70.48 112.39,69.85 v112.39,29.21 | v123.19,31.11 123.19,23.5
  Bottom 0.305: v112.39,29.21 121.28,29.21 v123.19,31.11 130.81,31.11
D29  (via drill 0.61 pad 1.02)
  Top 0.305: 118.11,79.38 118.11,78.11 114.3,74.3 114.3,69.85 113.67,69.22 v113.67,34.92 | v125.73,33.66 125.73,23.5
  Bottom 0.305: v113.67,34.92 118.75,34.92 120.02,33.66 v125.73,33.66 130.81,33.66
D30  (via drill 0.61 pad 1.02)
  Top 0.305: 123.19,79.38 123.19,76.2 121.92,74.93 v121.92,36.2 | 128.27,23.5 128.27,29.21 127.64,29.84 v127.64,36.2
  Bottom 0.305: v127.64,36.2 130.81,36.2 v121.92,36.2
D31
  Top 0.305: 128.27,79.38 128.27,76.2 127,74.93 127,40.64 128.91,38.73 | 130.81,23.5 130.81,28.57 128.91,30.48 128.91,38.73 | 128.91,38.73 130.81,38.73
D32
  Top 0.305: 133.35,79.38 133.35,76.2 132.08,74.93 132.08,67.31 133.99,65.41 133.99,41.27 | 133.99,41.27 130.81,41.27 | 133.99,41.27 133.99,28.57 133.35,27.94 133.35,23.5
GND  (via drill 0.61 pad 1.02)
  Top 0.305: 20.32,46.35 20.32,63.5 23.5,66.67 26.67,69.85 26.67,71.75 26.67,74.93 29.21,77.47 29.21,79.38 29.21,80.64 30.48,81.92 v30.48,87 | v19.68,29.21 v19.68,42.55 19.68,45.72 20.32,46.35 | 20.32,46.35 23.5,46.35 | 5.08,43.81 5.08,46.35 3.17,46.35 3.17,47.94 2.86,48.26 C3. | 5.08,43.81 3.17,43.81 | 5.08,36.2 5.08,43.81 | 5.08,36.2 3.17,36.2 | 5.08,36.2 5.08,33.66 3.17,33.66 2.54,33.66 1.27,32.38 1.27,28.57 3.17,26.67 3.17,23.5 3.17,20.32 | 46.99,43.81 48.9,45.72 48.9,46.99 46.99,48.9 | 102.87,48.9 104.78,46.99 104.78,45.72 102.87,43.81
  Top 0.61: 74.93,43.81 76.83,45.72 76.83,46.99 74.93,48.9 73.03,50.8 v73.03,67.94 | 54.61,71.75 54.61,74.3 57.15,76.83 57.15,79.38 55.24,81.28 v55.24,87 | 82.55,71.75 82.55,74.93 85.09,77.47 85.09,79.38 83.19,81.28 v83.19,87 | 110.49,71.75 110.49,74.93 113.03,77.47 113.03,79.38 111.12,81.28 v111.12,87 | 133.35,83.19 135.25,81.28 135.25,73.66 133.35,71.75 C5. | 57.15,23.5 57.15,26.67 58.1,27.62 58.1,30.8 58.42,31.11 59.69,31.11 | 29.21,23.5 29.21,30.48 29.84,31.11 31.75,31.11 | 85.09,23.5 85.09,26.35 86.04,27.3 86.04,30.8 86.36,31.11 87.63,31.11 | 115.57,31.11 114.62,31.11 113.98,30.48 113.98,26.67 113.03,25.72 113.03,23.5
  Top 1.016: 29.21,19.05 v29.21,18.41 29.21,23.5 | v54.61,18.41 54.61,15.88 | v54.61,18.41 54.61,15.88 | v57.15,18.41 57.15,23.5 | v54.61,18.41 54.61,15.88 | v82.55,18.41 82.55,15.88 | v82.55,18.41 82.55,15.88 | v85.09,18.41 85.09,23.5 | v82.55,18.41 82.55,15.88 | v113.03,18.41 113.03,23.5 | v110.49,18.41 110.49,15.88 | v26.67,18.41 26.67,15.88 v26.67,18.41 | v49.53,18.41 49.53,15.88 v49.53,18.41 | v77.47,18.41 77.47,15.88 v77.47,18.41 | v105.41,18.41 105.41,15.88 v105.41,18.41
  Bottom 0.305: v19.68,29.21 26.04,29.21 27.94,31.11 31.75,31.11 | v19.68,42.55 14.61,42.55 13.34,43.81 10.79,46.35 3.17,46.35 | 46.99,48.9 53.34,48.9 54.61,50.16 67.31,50.16 68.58,48.9 74.93,48.9 81.28,48.9 82.55,50.16 95.25,50.16 96.52,48.9 102.87,48.9 107.95,48.9 109.22,50.16 123.19,50.16 124.46,48.9 130.81,48.9 | R7. 33.02,98.42 33.02,97.16 31.11,95.25 31.11,92.71 30.48,92.08 30.48,87.63 v30.48,87 | R5. 40.01,98.42 40.01,97.16 38.1,95.25 38.1,87.63 | R3. 46.99,98.42 46.99,97.16 45.09,95.25 45.09,93.34 45.72,92.71 45.72,87.63 | R33. 53.98,98.42 53.98,97.16 52.07,95.25 52.07,87.63 | R31. 60.96,98.42 60.96,97.16 59.05,95.25 59.05,93.34 58.42,92.71 58.42,87.63 | R29. 67.94,98.42 67.94,97.16 66.04,95.25 66.04,87.63 | R27. 74.93,98.42 74.93,97.16 73.03,95.25 73.03,93.34 73.66,92.71 73.66,87.63 | R17. 81.92,98.42 81.92,97.16 80.01,95.25 80.01,87.63 | R15. 88.9,98.42 88.9,97.16 87,95.25 87,93.34 86.36,92.71 86.36,87.63 | R13. 95.89,98.42 95.89,97.16 93.98,95.25 93.98,87.63 | R11. 102.87,98.42 102.87,97.16 100.97,95.25 100.97,93.34 101.6,92.71 101.6,87.63 | R25. 109.86,98.42 109.86,97.16 107.95,95.25 107.95,87.63 | R23. 116.84,98.42 116.84,97.16 114.94,95.25 114.94,93.34 114.3,92.71 114.3,87.63 | R21. 123.83,98.42 123.83,97.16 121.92,95.25 121.92,87.63 | R19. 130.81,98.42 130.81,97.16 128.91,95.25 128.91,92.71 129.54,92.08 129.54,87.63 | 55.24,87.63 v55.24,87 | 83.19,87.63 v83.19,87 | 82.55,71.75 77.47,71.75 | 111.12,87.63 v111.12,87 | P3. 24.13,87.95 24.13,96.52 26.04,98.42 R9.
  Bottom 0.61: 54.61,71.75 49.53,71.75 | 110.49,71.75 105.41,71.75 | 82.55,71.75 77.47,71.75 77.47,69.22 76.2,67.94 v73.03,67.94
  Bottom 1.016: v26.67,18.41 26.35,18.41 | v29.21,18.41 v26.67,18.41 | v26.67,18.41 v49.53,18.41 v54.61,18.41 | v54.61,18.41 v57.15,18.41 | v54.61,18.41 v77.47,18.41 v82.55,18.41 | v82.55,18.41 v85.09,18.41 | v82.55,18.41 v105.41,18.41 v110.49,18.41 | v110.49,18.41 v113.03,18.41 | v110.49,18.41 v113.03,18.41 | v113.03,18.41 132.4,18.41 133.35,17.46 133.35,15.88 | C2. 83.19,31.11 87.63,31.11
  Bottom 1.27: 49.53,87.63 49.53,83.19 | 58.42,87.63 55.24,87.63 | 80.01,87.63 77.47,87.63 77.47,83.19 | 86.36,87.63 83.19,87.63 | 107.95,87.63 105.41,87.63 105.41,83.19 | 114.3,87.63 111.12,87.63 | 133.35,87 132.72,87.63 | 133.35,83.19 133.35,87 | 133.35,87 133.35,87.95 | 130.81,48.9 133.35,48.9 C5. 133.35,31.75 | 133.35,15.88 135.57,18.1 135.57,25.08 133.35,27.3 133.35,31.75 | 133.35,31.75 133.35,43.81 130.81,43.81
  Bottom 1.676: C4. 126.36,109.54 126.36,107 128.59,104.78 133.03,104.78 136.53,101.28 136.53,88.9 135.57,87.95 133.35,87.95
  Bottom 1.778: 132.72,87.63 129.54,87.63 121.92,87.63 114.3,87.63 107.95,87.63 101.6,87.63 93.98,87.63 86.36,87.63 80.01,87.63 73.66,87.63 66.04,87.63 58.42,87.63 52.07,87.63 49.53,87.63 45.72,87.63 38.1,87.63 30.48,87.63 26.67,87.63 26.04,87 P3. 25.08,82.23 23.18,80.33 19.05,80.33
  pour Bottom (isolate 0.5, no thermals): 0.64,92.08 25.4,92.08 27.3,90.17 27.3,82.23 24.13,79.06 24.13,70.17 22.23,68.26 14.92,68.26 13.97,67.31 13.97,57.78 13.02,56.83 8.89,56.83 7.3,55.24 1.91,55.24 0.64,55.24
  pour Top (isolate 0.5, no thermals): 0.64,92.08 25.4,92.08 27.3,90.17 27.3,82.23 24.13,79.06 24.13,70.17 22.23,68.26 14.92,68.26 13.97,67.31 13.97,57.78 13.02,56.83 8.89,56.83 7.3,55.24 0.64,55.24
N$1
  Top 0.305: 10.79,43.81 10.79,41.27 9.53,41.27 8.89,40.64 8.89,36.83 9.53,36.2 10.79,36.2
  Bottom 0.305: 10.79,41.27 13.34,41.27
N$2
  Top 0.305: R1. 13.34,27.3 11.43,25.4 11.43,18.73 13.02,17.14 19.05,17.14
N$3  (via drill 0.61 pad 1.02)
  Top 0.305: v19.05,55.88 19.05,47.62 18.41,46.99 v18.41,36.2 18.41,29.21 15.88,26.67 15.88,23.5
  Bottom 0.305: 15.88,56.52 18.41,56.52 v19.05,55.88 20.95,53.98 23.5,53.98 | v18.41,36.2 15.88,36.2 v18.41,36.2 | 23.5,33.66 20.95,36.2 v18.41,36.2 | R2. 15.88,23.5
N$4
  Top 0.305: 57.15,10.79 57.15,15.88
N$5
  Top 0.305: 59.69,10.79 59.69,15.88
N$6
  Top 0.305: 3.17,15.24 6.99,15.24 8.89,17.14 | 8.89,17.14 8.89,29.21 10.79,31.11 10.79,33.66 | P1. 8.89,17.14
N$7
  Top 0.305: 62.23,10.79 62.23,15.88
N$8
  Top 0.305: 64.77,10.79 64.77,15.88
N$9
  Top 0.305: 67.31,10.79 67.31,15.88
N$10
  Top 0.305: 69.85,10.79 69.85,15.88
N$11
  Top 0.305: 72.39,10.79 72.39,15.88
N$12
  Top 0.305: 74.93,10.79 74.93,15.88
N$13
  Top 0.305: 29.21,10.79 29.21,15.88
N$14
  Top 0.305: 31.75,10.79 31.75,15.88
N$15
  Top 0.305: 34.29,10.79 34.29,15.88
N$16
  Top 0.305: 36.83,10.79 36.83,15.88
N$17
  Top 0.305: 39.37,10.79 39.37,15.88
N$18
  Top 0.305: 41.91,10.79 41.91,15.88
N$19
  Top 0.305: 44.45,10.79 44.45,15.88
N$20
  Top 0.305: 46.99,10.79 46.99,15.88
N$21
  Top 0.305: R-SIL1. LED_1-8.
N$22
  Top 0.305: 31.75,2.54 31.75,8.26
N$23
  Top 0.305: 34.29,2.54 34.29,8.26
N$24
  Top 0.305: 36.83,2.54 36.83,8.26
N$25
  Top 0.305: 39.37,2.54 39.37,8.26
N$26
  Top 0.305: 41.91,8.57 41.91,8.26 41.91,2.54
N$27
  Top 0.305: 44.45,2.54 44.45,8.26
N$28
  Top 0.305: 46.99,2.54 46.99,8.26
N$29
  Top 0.305: R-SIL2. LED_9-16.
N$30
  Top 0.305: 59.69,2.54 59.69,8.26
N$31
  Top 0.305: 62.23,2.54 62.23,8.26
N$32
  Top 0.305: 64.77,2.54 64.77,8.26
N$33
  Top 0.305: 67.31,2.54 67.31,8.26
N$34
  Top 0.305: 69.85,2.54 69.85,8.26
N$35
  Top 0.305: 72.39,2.54 72.39,8.26
N$36
  Top 0.305: 74.93,2.54 74.93,8.26
N$37
  Top 0.305: 59.69,79.38 60.96,80.64 60.96,84.45 61.59,85.09 64.14,85.09 64.77,84.45 64.77,83.19
N$38
  Top 0.305: 62.23,83.19 64.77,79.38
N$39  (via drill 0.61 pad 1.02)
  Top 0.305: v58.42,77.47 58.42,80.64 59.69,81.92 59.69,83.19
  Bottom 0.305: 69.85,79.38 67.94,77.47 v58.42,77.47
N$40  (via drill 0.61 pad 1.02)
  Top 0.305: v73.66,85.09 73.66,80.64 74.93,79.38
  Bottom 0.305: 57.15,83.19 59.05,85.09 v73.66,85.09
N$41
  Top 0.305: 67.31,83.19 67.31,81.92 66.04,80.64 66.04,77.47 63.5,74.93 60.96,74.93 59.69,73.66 59.69,71.75
N$42  (via drill 0.61 pad 1.02)
  Top 0.305: 69.85,83.19 68.58,81.92 v68.58,73.66
  Bottom 0.305: v68.58,73.66 65.41,73.66 64.77,73.03 64.77,71.75
N$43
  Top 0.305: 72.39,83.19 71.12,81.92 71.12,76.2 69.85,74.93 69.85,71.75
N$44
  Top 0.305: 74.93,83.19 76.2,81.92 76.2,77.47 74.93,76.2 74.93,71.75
N$45
  Top 0.305: 85.09,10.79 85.09,15.88
N$46
  Top 0.305: 87.63,10.79 87.63,15.88
N$47
  Top 0.305: 90.17,10.79 90.17,15.88
N$48
  Top 0.305: 92.71,10.79 92.71,15.88
N$49
  Top 0.305: 95.25,10.79 95.25,15.88
N$50
  Top 0.305: 97.79,10.79 97.79,15.88
N$51
  Top 0.305: 100.33,10.79 100.33,15.88
N$52
  Top 0.305: 102.87,10.79 102.87,15.88
N$53
  Top 0.305: 113.03,10.79 113.03,15.88
N$54
  Top 0.305: 115.57,10.79 115.57,15.88
N$55
  Top 0.305: 118.11,10.79 118.11,15.88
N$56
  Top 0.305: 120.65,10.79 120.65,15.88
N$57
  Top 0.305: 123.19,10.79 123.19,15.88
N$58
  Top 0.305: 125.73,10.79 125.73,15.88
N$59
  Top 0.305: 128.27,10.79 128.27,15.88
N$60
  Top 0.305: 130.81,10.79 130.81,15.88
N$61
  Top 0.305: R-SIL4. LED25-32.
N$62
  Top 0.305: 115.57,2.54 115.57,8.26
N$63
  Top 0.305: 118.11,2.54 118.11,8.26
N$64
  Top 0.305: 120.65,2.54 120.65,8.26
N$65
  Top 0.305: 123.19,2.54 123.19,8.26
N$66
  Top 0.305: 125.73,2.54 125.73,8.26
N$67
  Top 0.305: 128.27,2.54 128.27,8.26
N$68
  Top 0.305: 130.81,2.54 130.81,8.26
N$69
  Top 0.305: 115.57,79.38 116.84,80.64 116.84,84.14 117.79,85.09 120.02,85.09 120.65,84.45 120.65,83.19
N$70
  Top 0.305: 118.11,83.19 120.65,79.38
N$71  (via drill 0.61 pad 1.02)
  Top 0.305: 115.57,83.19 114.3,81.92 v114.3,77.47
  Bottom 0.305: 125.73,79.38 123.83,77.47 v114.3,77.47
N$72  (via drill 0.61 pad 1.02)
  Top 0.305: 130.81,79.38 129.54,80.64 v129.54,85.09
  Bottom 0.305: 113.03,83.19 114.94,85.09 v129.54,85.09
N$73
  Top 0.305: 123.19,83.19 121.92,81.92 121.92,77.47 119.06,74.61 116.84,74.61 115.57,73.34 115.57,71.75
N$74  (via drill 0.61 pad 1.02)
  Top 0.305: 125.73,83.19 124.46,81.92 v124.46,73.66
  Bottom 0.305: 120.65,71.75 122.56,73.66 v124.46,73.66
N$75
  Top 0.305: 128.27,83.19 127,81.92 127,77.15 125.73,75.88 125.73,71.75
N$76
  Top 0.305: 130.81,83.19 132.08,81.92 132.08,77.47 130.81,76.2 130.81,71.75
N$77
  Bottom 0.305: LED1. R35.
N$78
  Bottom 1.676: D1. P2.
N$79  (via drill 0.3 pad 2.18)
  other vias: 132.4,111.12
N$101
  Top 0.305: 31.75,79.38 33.02,80.64 33.02,84.45 33.66,85.09 36.2,85.09 36.83,84.45 36.83,83.19
N$102
  Top 0.305: 34.29,83.19 36.83,79.38
N$103  (via drill 0.61 pad 1.02)
  Top 0.305: v31.11,76.83 30.48,77.47 30.48,80.01 31.75,81.28 31.75,83.19
  Bottom 0.305: v31.11,76.83 41.27,76.83 41.91,77.47 41.91,79.38
N$104  (via drill 0.61 pad 1.02)
  Top 0.305: 29.21,83.19 27.94,81.92 27.94,78.11 v25.4,75.56 | v48.26,75.56 46.99,76.83 46.99,79.38
  Bottom 0.305: v25.4,75.56 v48.26,75.56
N$105
  Top 0.305: 39.37,83.19 39.37,81.92 38.1,80.64 38.1,78.11 34.92,74.93 33.02,74.93 31.75,73.66 31.75,71.75
N$106  (via drill 0.61 pad 1.02)
  Top 0.305: 41.91,83.19 41.91,81.92 40.64,80.64 v40.64,74.3
  Bottom 0.305: v40.64,74.3 37.47,74.3 36.83,73.66 36.83,71.75
N$107
  Top 0.305: 41.91,71.75 41.91,75.56 43.18,76.83 43.18,80.64 44.45,81.92 44.45,83.19
N$108
  Top 0.305: 46.99,71.75 46.99,75.56 45.72,76.83 45.72,80.64 46.99,81.92 46.99,83.19
N$109
  Top 0.305: R-SIL3. LED17-24.
N$110
  Top 0.305: 87.63,2.54 87.63,8.26
N$111
  Top 0.305: 90.17,2.54 90.17,8.26
N$112
  Top 0.305: 92.71,2.54 92.71,8.26
N$113
  Top 0.305: 95.25,2.54 95.25,8.26
N$114
  Top 0.305: 97.79,2.54 97.79,8.26
N$115
  Top 0.305: 100.33,2.54 100.33,8.26
N$116
  Top 0.305: 102.87,2.54 102.87,8.26
N$117
  Top 0.305: 87.63,79.38 88.9,80.64 88.9,84.45 89.53,85.09 92.08,85.09 92.71,84.45 92.71,83.19
N$118
  Top 0.305: 90.17,83.19 92.71,79.38
N$119  (via drill 0.61 pad 1.02)
  Top 0.305: v86.36,77.47 86.36,80.01 87.63,81.28 87.63,83.19
  Bottom 0.305: 97.79,79.38 95.89,77.47 v86.36,77.47
N$120  (via drill 0.61 pad 1.02)
  Top 0.305: 102.87,79.38 101.6,80.64 v101.6,85.09
  Bottom 0.305: v101.6,85.09 87,85.09 85.09,83.19
N$121
  Top 0.305: 95.25,83.19 93.98,81.92 93.98,77.47 91.44,74.93 88.9,74.93 87.63,73.66 87.63,71.75
N$122  (via drill 0.61 pad 1.02)
  Top 0.305: v96.52,73.34 96.52,80.33 97.79,81.6 97.79,83.19
  Bottom 0.305: 92.71,71.75 94.3,73.34 v96.52,73.34
N$123
  Top 0.305: 97.79,71.75 97.79,76.2 99.06,77.47 99.06,81.92 100.33,83.19
N$124
  Top 0.305: 102.87,71.75 102.87,75.25 104.14,76.52 104.14,81.92 102.87,83.19
P1
  Bottom 6.452: 9.53,103.5 9.53,96.2 3.17,96.2 3.17,103.5 9.21,103.5 9.21,103.19
  pour Bottom (isolate 0.5, no thermals): 0.32,118.43 48.26,118.43 48.26,112.71 46.04,110.49 26.35,110.49 24.13,107.63 24.13,92.71 0.32,92.71
  pour Top (isolate 0.5, no thermals): 0.32,118.43 48.58,118.43 48.58,112.71 46.35,110.49 26.67,110.49 24.45,107.63 24.45,92.71 0.32,92.71
V_IN
  Top 1.422: 19.05,98.11 19.05,87.31 22.86,83.5 22.86,78.74 21.91,77.79 19.05,77.79
  Bottom 1.016: 95.89,111.12 95.89,113.67 98.42,113.67 99.38,113.67 98.74,114.94 | BULB-CON. 100.97,113.67 100.01,113.67 100.65,114.94 100.33,114.94
  Bottom 1.27: 100.33,114.94 100.33,113.67
  Bottom 1.676: 98.42,113.67 98.42,111.12 | 100.97,113.67 100.97,111.12 | 103.5,111.12 BULB-CON. 100.33,113.67 | 95.89,111.12 95.89,113.67 99.38,113.67 | 98.74,114.94 100.33,114.94 109.22,114.94 111.12,113.03 117.79,113.03 | 99.38,113.67 100.01,113.67 | 99.38,113.67 98.11,116.52 53.02,116.52 51.44,114.62 51.44,111.44 49.53,109.54 28.89,109.54 27.62,108.27 27.62,102.55 26.04,100.97 24.77,100.97 21.91,98.11 19.05,98.11

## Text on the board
Top: + | V+ | GND | + | + | + | LED | +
